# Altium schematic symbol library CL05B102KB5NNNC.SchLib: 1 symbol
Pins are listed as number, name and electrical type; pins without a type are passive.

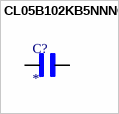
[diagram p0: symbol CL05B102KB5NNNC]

## CL05B102KB5NNNC
designator C?
1000 pF Â±10% 50V Ceramic Capacitor X7R 0402 (1005 Metric); MF: Samsung Electro-Mechanics; MP: CL05B102KB5NNNC
footprint CAPC1005X55N
pins: 1, 2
